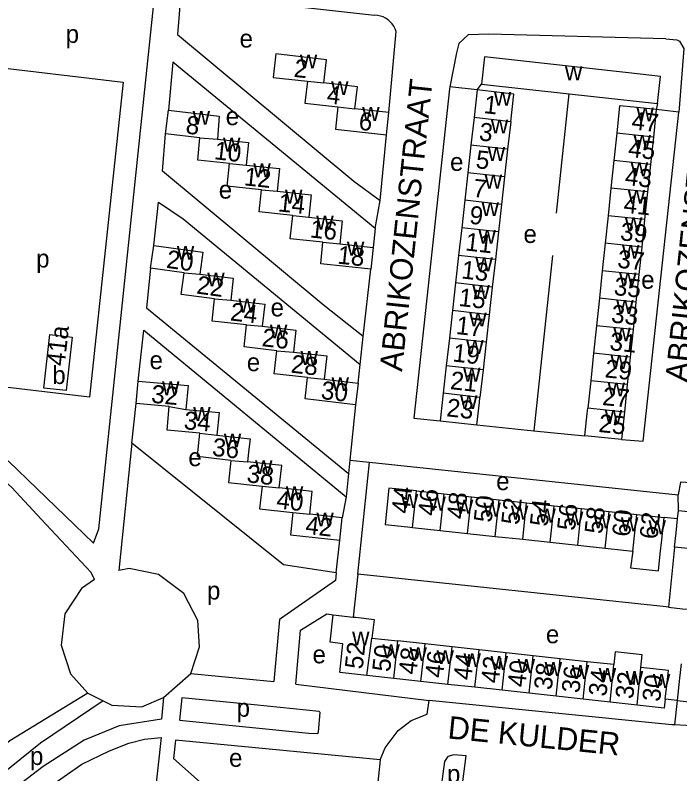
# Model space of a CAD drawing. Extents: x 161936 to 163647, y 386450 to 388633.
# Drawn here: x 162605.5 to 162752.9, y 387928 to 388096.2 of the extents above; entities that cross this region are included whole.
import ezdxf

# ---------------------------------------------------------------- set-up
doc = ezdxf.new("R2010")
doc.units = 0
for name, color, linetype in [('BLT_Basislijn', 7, 'Continuous'), ('BLT_Bebouwing', 7, 'Continuous'), ('BLT_Centroide', 7, 'Continuous'), ('BLT_Huisnummer', 7, 'Continuous'), ('BLT_Huisnummer_ tussenligend', 7, 'Continuous'), ('BLT_Onderverdeling_panden', 7, 'Continuous'), ('BLT_Straatnaam', 7, 'Continuous')]:
    doc.layers.add(name, color=color, linetype=linetype)

msp = doc.modelspace()

# ---------------------------------------------------------------- linework, layer by layer
at = {"layer": 'BLT_Basislijn'}
for p, q in [((162642.24, 388101.06), (162685.22, 388096.21)), ((162688.43, 388074.62), (162689.99, 388092.64)), ((162707.96, 388079.66), (162701.89, 388080.31)), ((162707.96, 388079.66), (162708.92, 388080.95)), ((162725.6, 388052.32), (162728.39, 388078.79)), ((162747.95, 388076.62), (162747.68, 388075.31)), ((162752.67, 388074.76), (162747.68, 388075.31)), ((162686.44, 388055.12), (162687.85, 388069.68)), ((162685.39, 388048.94), (162686.44, 388055.12)), ((162685.39, 388048.94), (162684.92, 388044.75)), ((162724.67, 388042.92), (162720.51, 388004.11)), ((162682.73, 388024.97), (162684.41, 388039.9)), ((162682.03, 388018.78), (162682.73, 388024.97)), ((162681.57, 388014.68), (162682.03, 388018.78)), ((162631.44, 388001.37), (162632.35, 388010.11)), ((162681.02, 388009.86), (162679.74, 387997.58)), ((162707.92, 388005.38), (162720.51, 388004.11)), ((162720.51, 388004.11), (162731.89, 388002.96)), ((162631.44, 388001.37), (162628.49, 387973.1)), ((162679.74, 387997.58), (162679.43, 387994.6)), ((162679.74, 387997.58), (162684.13, 387997.12)), ((162681.53, 387972.3), (162684.13, 387997.12)), ((162684.13, 387997.12), (162752.54, 387989.92)), ((162679.43, 387994.6), (162678.96, 387989.46)), ((162752.63, 387986.45), (162752.54, 387989.92)), ((162752.43, 387984.54), (162749.44, 387984.88)), ((162676.75, 387972.59), (162677.54, 387979.8)), ((162751.77, 387978.32), (162750.42, 387964.97)), ((162681.53, 387972.3), (162680.51, 387962.79)), ((162644.46, 387950.31), (162662.92, 387948.53)), ((162667.8, 387947.92), (162697.31, 387944.28)), ((162621.68, 387945.88), (162625.03, 387944.2)), ((162752.33, 387944.3), (162749.69, 387944.62)), ((162752.33, 387944.3), (162751.76, 387938.86)), ((162800.15, 387936.39), (162751.76, 387938.86)), ((162686.47, 387931.15), (162684.54, 387913.09))]:
    msp.add_line(p, q, dxfattribs=at)
for points in [[(162593.73, 388002.33), (162598.24, 388000.78), (162600, 387999.74), (162604.06, 387997.34), (162622.92, 387979.16), (162624.11, 387982.32), (162636.56, 388101.7)], [(162642.24, 388101.06), (162641.51, 388091.95)], [(162689.99, 388092.64), (162689.77, 388093.23), (162689.48, 388093.79), (162689.12, 388094.31), (162688.7, 388094.78), (162688.22, 388095.19), (162687.69, 388095.54), (162687.12, 388095.83), (162686.53, 388096.03), (162685.91, 388096.16), (162685.22, 388096.21)], [(162641.51, 388091.95), (162680.64, 388059.45), (162686.44, 388055.12)], [(162749.82, 388091.01), (162710.57, 388092.06), (162705.97, 388091.85), (162703.92, 388089.98), (162703.37, 388087.89), (162701.89, 388080.31)], [(162749.82, 388091.01), (162752.24, 388090.78), (162752.82, 388090.46), (162753.82, 388088.81), (162752.77, 388075.61), (162752.67, 388074.76)], [(162598.32, 388085.1), (162629.52, 388081.37), (162622.01, 388011.53), (162590.77, 388015.27)], [(162685.39, 388048.94), (162640.52, 388085.85), (162639.51, 388075.15)], [(162701.89, 388080.31), (162701.81, 388079.92), (162693.95, 388006.9), (162699.77, 388006.28)], [(162739.99, 388002.14), (162744.78, 388001.76), (162752.67, 388074.76)], [(162682.73, 388024.97), (162673.8, 388032.01), (162638.21, 388061.63), (162638.9, 388069.92)], [(162636.27, 388045.17), (162637.29, 388054.78), (162642.78, 388051.11), (162682.03, 388018.78)], [(162635.58, 388040.14), (162634.67, 388031.36), (162679.43, 387994.6)], [(162632.81, 388015.12), (162634.04, 388026.39), (162678.96, 387989.46)], [(162676.75, 387972.59), (162665.02, 387974.37), (162631.44, 388001.37)], [(162611.3, 387984.51), (162604.76, 387991.48), (162601.11, 387994.73), (162600, 387995.27), (162597.43, 387996.52), (162593.47, 387997.98), (162590.82, 387998), (162588.04, 387998.3), (162586.55, 387992.05), (162568.7, 387918.58), (162570.36, 387917.56), (162582.35, 387916.2)], [(162756.59, 387992.44), (162753.04, 387992.69), (162752.54, 387989.92)], [(162678.96, 387989.46), (162678.08, 387984.79)], [(162623.13, 387971.08), (162622.38, 387972.68), (162611.3, 387984.51)], [(162646.39, 387956.21), (162646.01, 387962.04), (162642.95, 387968), (162637.34, 387972.25), (162630.78, 387973.58), (162628.49, 387973.1)], [(162676.75, 387972.59), (162676.57, 387970.92), (162664.17, 387962.23), (162662.92, 387948.53)], [(162750.42, 387964.97), (162749.91, 387965.03), (162681.53, 387972.3)], [(162623.13, 387971.08), (162620.21, 387969.13), (162616.57, 387963.51), (162615.7, 387956.52), (162617.82, 387950.17), (162621.68, 387945.88)], [(162750.42, 387964.97), (162753.54, 387964.62), (162754.56, 387964.51)], [(162667.8, 387947.92), (162668.83, 387959.87), (162674.66, 387963.47), (162676.07, 387963.27)], [(162644.46, 387950.31), (162646.39, 387956.21)], [(162638.43, 387944.92), (162644.46, 387950.31)], [(162621.68, 387945.88), (162604.35, 387935.32), (162600, 387931.77), (162591.95, 387925.2), (162582.35, 387916.2)], [(162638.43, 387944.92), (162637.96, 387940.12), (162628.61, 387938.66), (162620.85, 387935.51), (162611.78, 387929.69), (162600, 387920.7), (162595.6, 387917.34), (162593.26, 387916.38), (162590.29, 387915.65), (162588.26, 387915.51)], [(162626.96, 387943.24), (162633.65, 387942.91), (162638.43, 387944.92)], [(162642.5, 387944.9), (162641.94, 387939.9)], [(162658.5, 387943.31), (162642.5, 387944.9)], [(162625.03, 387944.2), (162611.14, 387934.81), (162600, 387925.91), (162591.1, 387918.4), (162588.26, 387915.51)], [(162625.03, 387944.2), (162626.96, 387943.24)], [(162641.94, 387939.9), (162670.65, 387937.02), (162672.64, 387937), (162672.8, 387937.32), (162673.2, 387941.65), (162672.95, 387941.87), (162658.5, 387943.31)], [(162686.47, 387931.15), (162687.55, 387933.83), (162690.47, 387937.65), (162693.35, 387939.87), (162696.92, 387941.29), (162697.31, 387944.28)], [(162751.76, 387938.86), (162751.15, 387938.89), (162697.31, 387944.28)], [(162572.51, 387839.56), (162579.82, 387902.59), (162580.93, 387906.3), (162584.46, 387910.71), (162589.81, 387910.51), (162594.97, 387911.7), (162597.82, 387913.14), (162600, 387914.61), (162612.48, 387924.69), (162620.33, 387930.16), (162626.47, 387933.12), (162630.71, 387934.81), (162634.24, 387935.74), (162637.93, 387936.08), (162622.64, 387796.75)], [(162641.08, 387935.49), (162640.62, 387931.4)], [(162686.47, 387931.15), (162641.08, 387935.49)], [(162640.62, 387931.4), (162677.61, 387898.59), (162682.5, 387894.63)], [(162704.6, 387924.63), (162705.56, 387931.99), (162702.83, 387932.23), (162701.49, 387931.84), (162700.73, 387930.8), (162699.43, 387920.9)]]:
    msp.add_lwpolyline(points, dxfattribs=at)
at = {"layer": 'BLT_Bebouwing'}
for p, q in [((162747.95, 388076.62), (162748.62, 388082.67)), ((162707.96, 388079.66), (162707.28, 388073.53)), ((162708.92, 388080.95), (162728.39, 388078.79)), ((162728.39, 388078.79), (162747.95, 388076.62)), ((162638.9, 388069.92), (162639.51, 388075.15)), ((162688.43, 388074.62), (162680.86, 388075.5)), ((162687.85, 388069.68), (162688.43, 388074.62)), ((162747.68, 388075.31), (162747.05, 388069.22)), ((162707.28, 388073.53), (162706.6, 388067.42)), ((162715.42, 388072.62), (162714.74, 388066.51)), ((162646.46, 388069.04), (162638.9, 388069.92)), ((162738.92, 388070.08), (162738.28, 388063.98)), ((162747.05, 388069.22), (162746.4, 388063.12)), ((162706.6, 388067.42), (162705.91, 388061.31)), ((162714.74, 388066.51), (162714.05, 388060.4)), ((162738.28, 388063.98), (162737.64, 388057.88)), ((162746.4, 388063.12), (162745.76, 388057.03)), ((162705.91, 388061.31), (162705.23, 388055.19)), ((162714.05, 388060.4), (162713.37, 388054.29)), ((162737.64, 388057.88), (162737.01, 388051.78)), ((162745.76, 388057.03), (162745.12, 388050.93)), ((162705.23, 388055.19), (162704.55, 388049.08)), ((162713.37, 388054.29), (162712.69, 388048.17)), ((162737.01, 388051.78), (162736.37, 388045.68)), ((162745.12, 388050.93), (162744.48, 388044.83)), ((162704.55, 388049.08), (162703.87, 388042.97)), ((162712.69, 388048.17), (162712.01, 388042.06)), ((162635.58, 388040.14), (162636.27, 388045.17)), ((162677.51, 388045.53), (162684.92, 388044.75)), ((162684.92, 388044.75), (162684.41, 388039.9)), ((162736.37, 388045.68), (162735.73, 388039.58)), ((162744.48, 388044.83), (162743.84, 388038.73)), ((162703.87, 388042.97), (162703.18, 388036.86)), ((162712.01, 388042.06), (162711.33, 388035.95)), ((162643.01, 388039.12), (162635.58, 388040.14)), ((162735.73, 388039.58), (162735.09, 388033.49)), ((162743.84, 388038.73), (162743.2, 388032.63)), ((162703.18, 388036.86), (162702.5, 388030.74)), ((162711.33, 388035.95), (162710.64, 388029.83)), ((162735.09, 388033.49), (162734.45, 388027.39)), ((162743.2, 388032.63), (162742.55, 388026.54)), ((162702.5, 388030.74), (162701.82, 388024.63)), ((162710.64, 388029.83), (162709.96, 388023.72)), ((162734.45, 388027.39), (162733.81, 388021.29)), ((162742.55, 388026.54), (162741.91, 388020.44)), ((162701.82, 388024.63), (162701.14, 388018.52)), ((162709.96, 388023.72), (162709.28, 388017.61)), ((162733.81, 388021.29), (162733.17, 388015.19)), ((162741.91, 388020.44), (162741.27, 388014.34)), ((162701.14, 388018.52), (162700.46, 388012.4)), ((162709.28, 388017.61), (162708.6, 388011.49)), ((162674.05, 388015.54), (162681.57, 388014.68)), ((162632.35, 388010.11), (162632.81, 388015.12)), ((162681.57, 388014.68), (162681.02, 388009.86)), ((162733.17, 388015.19), (162732.53, 388009.09)), ((162741.27, 388014.34), (162740.63, 388008.24)), ((162700.46, 388012.4), (162699.77, 388006.28)), ((162639.71, 388009.44), (162632.35, 388010.11)), ((162740.63, 388008.24), (162739.99, 388002.14)), ((162699.77, 388006.28), (162707.92, 388005.38)), ((162739.99, 388002.14), (162731.89, 388002.96)), ((162694.53, 387990.74), (162700.63, 387990.08)), ((162700.63, 387990.08), (162706.74, 387989.43)), ((162706.74, 387989.43), (162712.84, 387988.78)), ((162712.84, 387988.78), (162718.94, 387988.13)), ((162718.94, 387988.13), (162725.04, 387987.48)), ((162725.04, 387987.48), (162731.14, 387986.83)), ((162731.14, 387986.83), (162737.25, 387986.18)), ((162678.08, 387984.79), (162670.84, 387985.58)), ((162737.25, 387986.18), (162743.35, 387985.53)), ((162743.35, 387985.53), (162749.44, 387984.88)), ((162752.43, 387984.54), (162752.63, 387986.45)), ((162752.63, 387986.45), (162758.74, 387985.8)), ((162677.54, 387979.8), (162678.08, 387984.79)), ((162693.67, 387982.64), (162699.77, 387981.99)), ((162699.77, 387981.99), (162705.87, 387981.34)), ((162705.87, 387981.34), (162711.97, 387980.68)), ((162711.97, 387980.68), (162718.08, 387980.03)), ((162718.08, 387980.03), (162724.18, 387979.38)), ((162724.18, 387979.38), (162730.28, 387978.73)), ((162730.28, 387978.73), (162736.38, 387978.08)), ((162736.38, 387978.08), (162742.48, 387977.43)), ((162757.88, 387977.67), (162751.77, 387978.32)), ((162676.07, 387963.27), (162680.51, 387962.79)), ((162684.65, 387958.14), (162690.42, 387957.5)), ((162696.42, 387956.84), (162690.42, 387957.5)), ((162702.42, 387956.18), (162696.42, 387956.84)), ((162708.41, 387955.53), (162702.42, 387956.18)), ((162714.41, 387954.87), (162708.41, 387955.53)), ((162720.41, 387954.21), (162714.41, 387954.87)), ((162726.4, 387953.55), (162720.41, 387954.21)), ((162732.4, 387952.89), (162726.4, 387953.55)), ((162738.29, 387952.25), (162732.4, 387952.89)), ((162683.51, 387949.85), (162677.52, 387950.5)), ((162689.51, 387949.19), (162683.51, 387949.85)), ((162695.51, 387948.53), (162689.51, 387949.19)), ((162701.5, 387947.87), (162695.51, 387948.53)), ((162707.5, 387947.21), (162701.5, 387947.87)), ((162713.5, 387946.55), (162707.5, 387947.21)), ((162719.49, 387945.9), (162713.5, 387946.55)), ((162725.49, 387945.24), (162719.49, 387945.9)), ((162731.49, 387944.58), (162725.49, 387945.24)), ((162737.49, 387943.92), (162731.49, 387944.58)), ((162743.48, 387943.26), (162737.49, 387943.92)), ((162752.33, 387944.3), (162758.32, 387943.63))]:
    msp.add_line(p, q, dxfattribs=at)
for points in [[(162673.97, 388081.23), (162674.57, 388086.34), (162663.34, 388087.64), (162662.74, 388082.45), (162670.34, 388081.57)], [(162748.62, 388082.67), (162741.52, 388083.46), (162709.6, 388087.01), (162708.92, 388080.95)], [(162670.34, 388081.57), (162669.78, 388076.73), (162677.1, 388075.88)], [(162680.86, 388075.5), (162681.42, 388080.37), (162673.97, 388081.23)], [(162715.42, 388072.62), (162716.1, 388078.73), (162712.93, 388079.09), (162707.96, 388079.66)], [(162747.68, 388075.31), (162742.71, 388075.83), (162739.56, 388076.16), (162738.92, 388070.08)], [(162639.51, 388075.15), (162650.74, 388073.86), (162650.43, 388068.74)], [(162677.1, 388075.88), (162676.54, 388070.98), (162687.85, 388069.68)], [(162653.05, 388063.36), (162646.01, 388064.12), (162646.46, 388069.04)], [(162650.43, 388068.74), (162657.26, 388068.02), (162656.73, 388062.99)], [(162660.14, 388057.52), (162652.52, 388058.32), (162653.05, 388063.36)], [(162656.73, 388062.99), (162664.17, 388062.21), (162663.65, 388057.2)], [(162667.1, 388051.81), (162659.62, 388052.6), (162660.14, 388057.52)], [(162663.65, 388057.2), (162671.16, 388056.41), (162670.63, 388051.44)], [(162673.78, 388045.88), (162666.55, 388046.64), (162667.1, 388051.81)], [(162670.63, 388051.44), (162678.05, 388050.66), (162677.51, 388045.53)], [(162684.41, 388039.9), (162673.28, 388041.08), (162673.78, 388045.88)], [(162636.27, 388045.17), (162647.16, 388043.68), (162646.49, 388038.82)], [(162649.75, 388033.34), (162642.35, 388034.34), (162643.01, 388039.12)], [(162646.49, 388038.82), (162653.89, 388037.92), (162653.33, 388033.06)], [(162656.85, 388027.57), (162649.2, 388028.41), (162649.75, 388033.34)], [(162653.33, 388033.06), (162660.89, 388032.19), (162660.32, 388027.27)], [(162663.56, 388021.85), (162656.29, 388022.68), (162656.85, 388027.57)], [(162660.32, 388027.27), (162667.77, 388026.41), (162667.22, 388021.54)], [(162613.24, 388025.4), (162618.2, 388024.83), (162616.84, 388013.01), (162611.87, 388013.55), (162613.24, 388025.4)], [(162670.39, 388015.9), (162662.98, 388016.75), (162663.56, 388021.85)], [(162667.22, 388021.54), (162674.64, 388020.69), (162674.05, 388015.54)], [(162681.02, 388009.86), (162669.85, 388011.14), (162670.39, 388015.9)], [(162632.81, 388015.12), (162643.88, 388014.1), (162643.4, 388008.83)], [(162707.92, 388005.38), (162708.47, 388010.35), (162708.6, 388011.49)], [(162646.46, 388003.59), (162639.24, 388004.26), (162639.71, 388009.44)], [(162643.4, 388008.83), (162650.79, 388008.15), (162650.25, 388003.14)], [(162731.89, 388002.96), (162732.41, 388007.93), (162732.53, 388009.09)], [(162653.34, 387997.51), (162645.98, 387998.36), (162646.13, 388000), (162646.46, 388003.59)], [(162650.25, 388003.14), (162657.64, 388002.33), (162657.38, 388000), (162657.08, 387997.24)], [(162653.34, 387997.51), (162652.81, 387992.6), (162660.28, 387991.79)], [(162664.09, 387991.43), (162664.64, 387996.41), (162657.08, 387997.24)], [(162660.28, 387991.79), (162659.73, 387986.75), (162667.1, 387985.95)], [(162670.84, 387985.58), (162671.39, 387990.63), (162664.09, 387991.43)], [(162694.53, 387990.74), (162688.43, 387991.39), (162687.57, 387983.29), (162692.54, 387982.76), (162693.67, 387982.64)], [(162667.1, 387985.95), (162666.56, 387981), (162677.54, 387979.8)], [(162742.48, 387977.43), (162741.96, 387973.67), (162748.18, 387973.01), (162748.58, 387976.78), (162748.91, 387979.91), (162749.44, 387984.88)], [(162751.77, 387978.32), (162752.11, 387981.48), (162752.43, 387984.54)], [(162677.52, 387950.5), (162678.21, 387956.88), (162675.4, 387957.19), (162676.07, 387963.27)], [(162680.51, 387962.79), (162681.04, 387962.73), (162685.11, 387962.28), (162684.65, 387958.14)], [(162744.26, 387951.59), (162744.57, 387954.43), (162738.6, 387955.08), (162738.29, 387952.25)], [(162749.69, 387944.62), (162750.02, 387947.58), (162750.38, 387950.92), (162744.26, 387951.59)], [(162753.23, 387952.39), (162752.88, 387949.27), (162752.33, 387944.3)], [(162749.69, 387944.62), (162749.47, 387942.6), (162743.48, 387943.26)]]:
    msp.add_lwpolyline(points, dxfattribs=at)
at = {"layer": 'BLT_Onderverdeling_panden'}
for p, q in [((162670.34, 388081.57), (162673.97, 388081.23)), ((162677.1, 388075.88), (162680.86, 388075.5)), ((162715.42, 388072.62), (162707.28, 388073.53)), ((162747.05, 388069.22), (162738.92, 388070.08)), ((162646.46, 388069.04), (162650.43, 388068.74)), ((162714.74, 388066.51), (162706.6, 388067.42)), ((162653.05, 388063.36), (162656.73, 388062.99)), ((162746.4, 388063.12), (162738.28, 388063.98)), ((162714.05, 388060.4), (162705.91, 388061.31)), ((162660.14, 388057.52), (162663.65, 388057.2)), ((162745.76, 388057.03), (162737.64, 388057.88)), ((162713.37, 388054.29), (162705.23, 388055.19)), ((162667.1, 388051.81), (162670.63, 388051.44)), ((162745.12, 388050.93), (162737.01, 388051.78)), ((162712.69, 388048.17), (162704.55, 388049.08)), ((162673.78, 388045.88), (162677.51, 388045.53)), ((162744.48, 388044.83), (162736.37, 388045.68)), ((162712.01, 388042.06), (162703.87, 388042.97)), ((162643.01, 388039.12), (162646.49, 388038.82)), ((162743.84, 388038.73), (162735.73, 388039.58)), ((162711.33, 388035.95), (162703.18, 388036.86)), ((162649.75, 388033.34), (162653.33, 388033.06)), ((162743.2, 388032.63), (162735.09, 388033.49)), ((162710.64, 388029.83), (162702.5, 388030.74)), ((162656.85, 388027.57), (162660.32, 388027.27)), ((162742.55, 388026.54), (162734.45, 388027.39)), ((162709.96, 388023.72), (162701.82, 388024.63)), ((162663.56, 388021.85), (162667.22, 388021.54)), ((162741.91, 388020.44), (162733.81, 388021.29)), ((162709.28, 388017.61), (162701.14, 388018.52)), ((162670.39, 388015.9), (162674.05, 388015.54)), ((162741.27, 388014.34), (162733.17, 388015.19)), ((162708.6, 388011.49), (162700.46, 388012.4)), ((162639.71, 388009.44), (162643.4, 388008.83)), ((162740.63, 388008.24), (162732.53, 388009.09)), ((162646.46, 388003.59), (162650.25, 388003.14)), ((162653.34, 387997.51), (162657.08, 387997.24)), ((162660.28, 387991.79), (162664.09, 387991.43)), ((162693.67, 387982.64), (162694.53, 387990.74)), ((162699.77, 387981.99), (162700.63, 387990.08)), ((162705.87, 387981.34), (162706.74, 387989.43)), ((162711.97, 387980.68), (162712.84, 387988.78)), ((162718.08, 387980.03), (162718.94, 387988.13)), ((162724.18, 387979.38), (162725.04, 387987.48)), ((162730.28, 387978.73), (162731.14, 387986.83)), ((162667.1, 387985.95), (162670.84, 387985.58)), ((162736.38, 387978.08), (162737.25, 387986.18)), ((162742.48, 387977.43), (162743.35, 387985.53)), ((162683.51, 387949.85), (162684.65, 387958.14)), ((162689.51, 387949.19), (162690.42, 387957.5)), ((162695.51, 387948.53), (162696.42, 387956.84)), ((162701.5, 387947.87), (162702.42, 387956.18)), ((162707.5, 387947.21), (162708.41, 387955.53)), ((162713.5, 387946.55), (162714.41, 387954.87)), ((162719.49, 387945.9), (162720.41, 387954.21)), ((162725.49, 387945.24), (162726.4, 387953.55)), ((162731.49, 387944.58), (162732.4, 387952.89)), ((162737.49, 387943.92), (162738.29, 387952.25)), ((162743.48, 387943.26), (162744.26, 387951.59))]:
    msp.add_line(p, q, dxfattribs=at)

# ---------------------------------------------------------------- texts
at = {"layer": 'BLT_Centroide'}
for s, p in [('p', (162616.73, 388090.08)), ('e', (162655.29, 388089.06)), ('w', (162668.66, 388084.44)), ('w', (162727.44, 388081.81)), ('w', (162675.59, 388078.53)), ('w', (162711.69, 388076.16)), ('w', (162644.88, 388071.94)), ('e', (162652.22, 388071.85)), ('w', (162682.48, 388072.78)), ('w', (162743.3, 388072.69)), ('w', (162711.01, 388070.03)), ('w', (162742.66, 388066.59)), ('w', (162651.62, 388066)), ('w', (162710.32, 388063.91)), ('e', (162701.97, 388061.71)), ('w', (162658.34, 388060.28)), ('w', (162742.02, 388060.5)), ('w', (162709.64, 388057.78)), ('e', (162650.68, 388055.56)), ('w', (162665.38, 388054.47)), ('w', (162741.38, 388054.41)), ('w', (162708.96, 388051.69)), ('w', (162672.3, 388048.69)), ('w', (162740.74, 388048.31)), ('w', (162708.28, 388045.56)), ('e', (162718.25, 388045.73)), ('w', (162679.09, 388042.91)), ('w', (162641.38, 388042)), ('w', (162740.1, 388042.22)), ('p', (162610.18, 388040.29)), ('w', (162707.59, 388039.47)), ('w', (162648.13, 388036.09)), ('w', (162739.46, 388036.09)), ('e', (162744.35, 388035.59)), ('w', (162706.91, 388033.34)), ('w', (162655.04, 388030.31)), ('e', (162662.17, 388029.45)), ('w', (162738.82, 388030)), ('w', (162706.23, 388027.22)), ('w', (162662.03, 388024.56)), ('w', (162738.18, 388023.91)), ('w', (162705.55, 388021.12)), ('e', (162635.33, 388017.76)), ('w', (162668.81, 388018.69)), ('w', (162737.55, 388017.81)), ('e', (162656.9, 388017.3)), ('b', (162613.77, 388014.46)), ('w', (162704.87, 388015)), ('w', (162675.7, 388012.88)), ('w', (162638.1, 388011.97)), ('w', (162736.91, 388011.72)), ('w', (162704.19, 388008.91)), ('w', (162645.01, 388006.28)), ('w', (162736.27, 388005.62)), ('w', (162651.8, 388000.41)), ('e', (162643.93, 387996.25)), ('w', (162658.72, 387994.47)), ('e', (162712.19, 387990.94)), ('w', (162665.55, 387988.69)), ('w', (162691.05, 387987)), ('w', (162697.16, 387986.38)), ('w', (162703.25, 387985.72)), ('w', (162709.36, 387985.06)), ('w', (162715.45, 387984.41)), ('w', (162672.32, 387982.88)), ('w', (162721.56, 387983.75)), ('w', (162727.66, 387983.09)), ('w', (162733.77, 387982.47)), ('w', (162739.86, 387981.81)), ('w', (162745.97, 387981.16)), ('p', (162648.07, 387966.67)), ('e', (162723.22, 387956.98)), ('w', (162680.25, 387956.5)), ('w', (162686.97, 387953.67)), ('e', (162671.47, 387952.53)), ('w', (162692.97, 387953.02)), ('w', (162698.97, 387952.36)), ('w', (162704.95, 387951.7)), ('w', (162710.95, 387951.05)), ('w', (162716.95, 387950.39)), ('w', (162722.95, 387949.72)), ('w', (162728.95, 387949.06)), ('w', (162734.94, 387948.41)), ('w', (162740.94, 387947.75)), ('w', (162746.94, 387947.09)), ('p', (162654.64, 387940.68)), ('p', (162608.82, 387929.99)), ('e', (162652.96, 387929.59)), ('p', (162701.28, 387926.02))]:
    msp.add_text(s, height=4, dxfattribs=at).set_placement(p)
at = {"layer": 'BLT_Huisnummer'}
for s, rotation, p in [('2', 353.4057, (162667.2, 388082.58)), ('1', 353.6351, (162709.32, 388074.54)), ('6', 353.4021, (162681.57, 388070.86)), ('47', 353.9928, (162742.09, 388070.93)), ('8', 353.408, (162643.22, 388070.01)), ('5', 353.6351, (162707.54, 388062.34)), ('12', 353.9902, (162656.15, 388058.53)), ('41', 353.9976, (162740.33, 388052.47)), ('9', 353.6351, (162706.12, 388050.03)), ('20', 352.1911, (162638.91, 388040.24)), ('18', 353.9915, (162676.88, 388041.17)), ('37', 353.998, (162738.95, 388040.26)), ('13', 353.6351, (162704.36, 388037.88)), ('24', 353.4602, (162653.1, 388028.57)), ('33', 353.9936, (162737.57, 388028.11)), ('17', 353.6351, (162703.15, 388025.57)), ('41a', 83.7776, (162616.51, 388018.31)), ('29', 353.9961, (162736.17, 388015.95)), ('32', 354.7515, (162635.6, 388010.32)), ('30', 353.4572, (162673.2, 388011.17)), ('23', 353.6845, (162701.05, 388007.32)), ('25', 354.232, (162734.78, 388003.84)), ('36', 353.3552, (162649.08, 387998.57)), ('44', 83.9092, (162692.95, 387985.59)), ('50', 83.9092, (162711.17, 387983.63)), ('54', 83.9092, (162723.61, 387982.76)), ('58', 83.9085, (162735.74, 387981.1)), ('62', 83.9142, (162747.93, 387979.93)), ('42', 353.7739, (162669.77, 387981.25)), ('52', 83.7339, (162682.58, 387951.11)), ('46', 83.74, (162700.36, 387949.18)), ('42', 83.7393, (162712.77, 387947.98)), ('38', 83.7317, (162724.52, 387946.51)), ('34', 83.7317, (162736.62, 387945.08)), ('30', 83.7369, (162748.53, 387943.9))]:
    msp.add_text(s, height=4, rotation=rotation, dxfattribs=at).set_placement(p)
at = {"layer": 'BLT_Huisnummer_ tussenligend'}
for s, rotation, p in [('4', 353.4057, (162674.51, 388076.73)), ('3', 353.6351, (162708.27, 388068.49)), ('10', 353.408, (162649.53, 388064.32)), ('45', 353.9976, (162741.35, 388064.83)), ('43', 353.9976, (162740.62, 388058.61)), ('7', 353.6351, (162706.92, 388056)), ('14', 353.9902, (162663.71, 388052.75)), ('16', 353.9902, (162670.79, 388046.97)), ('39', 353.998, (162739.57, 388046.35)), ('11', 353.6351, (162705.21, 388044.09)), ('22', 352.1911, (162645.6, 388034.54)), ('35', 353.9936, (162738.18, 388034.21)), ('15', 353.6351, (162703.75, 388031.78)), ('26', 353.4602, (162660.1, 388022.87)), ('31', 353.9961, (162737.23, 388022)), ('19', 353.6351, (162702.43, 388019.47)), ('28', 353.4602, (162666.54, 388017)), ('21', 353.6351, (162701.87, 388013.35)), ('27', 354.232, (162735.62, 388009.82)), ('34', 354.7515, (162642.83, 388004.46)), ('38', 353.3552, (162656.74, 387992.7)), ('40', 353.3552, (162663.32, 387986.92)), ('46', 83.9092, (162698.8, 387985.11)), ('48', 83.9092, (162705.2, 387984.37)), ('52', 83.9092, (162717.27, 387983.13)), ('56', 83.9085, (162729.65, 387981.83)), ('60', 83.9085, (162741.84, 387980.48)), ('50', 83.74, (162688.66, 387950.52)), ('48', 83.74, (162694.51, 387949.92)), ('44', 83.7393, (162706.67, 387948.69)), ('40', 83.7317, (162718.67, 387947.11)), ('36', 83.7317, (162730.65, 387945.82)), ('32', 83.7369, (162742.56, 387944.52))]:
    msp.add_text(s, height=4, rotation=rotation, dxfattribs=at).set_placement(p)
at = {"layer": 'BLT_Straatnaam'}
for s, rotation, p in [('ABRIKOZENSTRAAT', 84.0108, (162691.31, 388017.11)), ('ABRIKOZENSTRAAT', 84.0108, (162754.63, 388014.72)), ('DE KULDER', 354.2907, (162701.32, 387935.9))]:
    msp.add_text(s, height=5, rotation=rotation, dxfattribs=at).set_placement(p)

doc.saveas('drawing.dxf')
